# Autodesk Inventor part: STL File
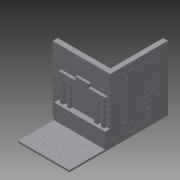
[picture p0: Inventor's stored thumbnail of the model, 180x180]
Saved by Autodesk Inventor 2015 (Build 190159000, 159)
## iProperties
Created: 2015-05
Part Number: STL File
Material: Generic
Document SubType Name: Modeling
Designer: TREINA5
Density: 1 g/cm^3
Appearance: Default
Author: TREINA5
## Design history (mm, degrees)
derived "Montagem.iam"
body "Solid1"
node "Parede.ipt:1"
node "Azulejo (1).ipt:1"
node "Azulejo (1).ipt:2"
node "Azulejo (1).ipt:3"
node "Azulejo (1).ipt:4"
node "Azulejo (1).ipt:5"
node "Azulejo (1).ipt:6"
node "Azulejo (1).ipt:7"
node "Azulejo (1).ipt:8"
node "Azulejo (1).ipt:9"
node "Azulejo (1).ipt:10"
node "Azulejo (1).ipt:11"
node "Azulejo (1).ipt:12"
node "Azulejo (1).ipt:13"
node "Azulejo (1).ipt:14"
node "Azulejo (1).ipt:15"
node "Azulejo (1).ipt:16"
node "Azulejo (1).ipt:17"
node "Azulejo (1).ipt:20"
node "Azulejo (1).ipt:21"
node "Azulejo (1).ipt:22"
node "Azulejo (1).ipt:23"
node "Azulejo (1).ipt:24"
node "Azulejo (1).ipt:25"
node "Azulejo (1).ipt:26"
node "Azulejo (1).ipt:27"
node "Azulejo (1).ipt:30"
node "Azulejo (1).ipt:31"
node "Azulejo (1).ipt:32"
node "Azulejo (9).ipt:2"
node "Azulejo (10).ipt:1"
node "Azulejo (10).ipt:2"
node "Azulejo (9).ipt:3"
node "Azulejo (9).ipt:4"
node "Azulejo (9).ipt:5"
node "Azulejo (1).ipt:33"
node "Azulejo (1).ipt:34"
node "Azulejo (1).ipt:35"
node "Azulejo (1).ipt:36"
node "Azulejo (1).ipt:37"
node "Azulejo (1).ipt:38"
node "Azulejo (1).ipt:39"
node "Azulejo (1).ipt:40"
node "Azulejo (1).ipt:41"
node "Azulejo (1).ipt:44"
node "Azulejo (1).ipt:48"
node "Azulejo (1).ipt:49"
node "Azulejo (3).ipt:1"
node "Azulejo (2).ipt:1"
node "Azulejo (4).ipt:1"
node "Azulejo (5).ipt:1"
node "Azulejo (5).ipt:2"
node "Azulejo (5).ipt:3"
node "Azulejo (5).ipt:4"
node "Azulejo (5).ipt:5"
node "Azulejo (5).ipt:6"
node "Azulejo (5).ipt:7"
node "Azulejo (7).ipt:1"
node "Azulejo (5).ipt:8"
node "Azulejo (5).ipt:9"
node "Azulejo (5).ipt:10"
node "Azulejo (5).ipt:11"
node "Azulejo (1).ipt:50"
node "Azulejo (2).ipt:2"
node "Azulejo (2).ipt:3"
node "Azulejo (6).ipt:1"
node "Azulejo (2).ipt:4"
node "Azulejo (2).ipt:5"
node "Azulejo (2).ipt:6"
node "Azulejo (8).ipt:1"
node "Azulejo (8).ipt:2"
node "Azulejo (1).ipt:51"
node "Azulejo (1).ipt:52"
node "Azulejo (1).ipt:53"
node "Azulejo (1).ipt:54"
node "Azulejo (1).ipt:55"
node "Azulejo (1).ipt:56"
node "Azulejo (1).ipt:57"
node "Azulejo (1).ipt:58"
node "Azulejo (1).ipt:59"
node "Azulejo (1).ipt:60"
node "Azulejo (1).ipt:61"
node "Azulejo (1).ipt:62"
node "Azulejo (1).ipt:63"
node "Azulejo (1).ipt:64"
node "Azulejo (1).ipt:65"
node "Azulejo (1).ipt:66"
node "Azulejo (1).ipt:67"
node "Azulejo (1).ipt:68"
node "Azulejo (1).ipt:69"
node "Azulejo (1).ipt:70"
node "Azulejo (1).ipt:73"
node "Azulejo (1).ipt:74"
node "Azulejo (1).ipt:75"
node "Azulejo (1).ipt:76"
node "Azulejo (1).ipt:77"
node "Azulejo (1).ipt:78"
node "Azulejo (1).ipt:79"
node "Azulejo (1).ipt:80"
node "Azulejo (1).ipt:81"
node "Azulejo (1).ipt:82"
node "Azulejo (1).ipt:83"
node "Azulejo (1).ipt:84"
node "Azulejo (1).ipt:85"
node "Azulejo (1).ipt:86"
node "Azulejo (1).ipt:87"
node "Azulejo (1).ipt:88"
node "Azulejo (1).ipt:89"
node "Azulejo (1).ipt:90"
node "Azulejo (1).ipt:91"
node "Azulejo (1).ipt:92"
node "Azulejo (1).ipt:93"
node "Azulejo (1).ipt:94"
node "Azulejo (1).ipt:95"
node "Azulejo (1).ipt:96"
node "Azulejo (1).ipt:97"
node "Azulejo (1).ipt:98"
node "Azulejo (1).ipt:99"
node "Azulejo (1).ipt:100"
node "Azulejo (1).ipt:101"
node "Azulejo (1).ipt:102"
node "Azulejo (1).ipt:103"
node "Azulejo (1).ipt:104"
node "Azulejo (1).ipt:105"
node "Azulejo (1).ipt:106"
node "Azulejo (1).ipt:107"
node "Azulejo (1).ipt:108"
node "Azulejo (1).ipt:109"
node "Azulejo (1).ipt:110"
node "Azulejo (1).ipt:111"
node "Azulejo (1).ipt:112"
node "Azulejo (1).ipt:113"
node "Azulejo (1).ipt:114"
node "Azulejo (1).ipt:115"
node "Azulejo (1).ipt:116"
node "Azulejo (1).ipt:117"
node "Azulejo (1).ipt:118"
node "Azulejo (1).ipt:119"
node "Azulejo (1).ipt:120"
node "Azulejo (1).ipt:121"
node "Azulejo (1).ipt:122"
node "Azulejo (1).ipt:123"
node "Azulejo (1).ipt:124"
node "Azulejo (1).ipt:125"
node "Azulejo (1).ipt:126"
node "Azulejo (1).ipt:127"
node "Azulejo (1).ipt:128"
node "Azulejo (1).ipt:129"
node "Azulejo (1).ipt:130"
node "Azulejo (1).ipt:131"
node "Azulejo (1).ipt:132"
node "Azulejo (1).ipt:133"
node "Azulejo (1).ipt:134"
node "Azulejo (1).ipt:136"
node "Azulejo (1).ipt:137"
node "Azulejo (1).ipt:138"
node "Azulejo (1).ipt:140"
node "Azulejo (11).ipt:1"
node "Azulejo (12).ipt:1"
node "Azulejo (13).ipt:1"
node "Azulejo (14).ipt:1"
node "Azulejo (15).ipt:1"
node "Azulejo (16).ipt:1"
node "Azulejo (1).ipt:141"
node "Azulejo (1).ipt:142"
node "Azulejo (1).ipt:143"
node "Azulejo (1).ipt:144"
node "Azulejo (1).ipt:145"
node "Azulejo (1).ipt:146"
node "Azulejo (17).ipt:1"
node "Azulejo (18).ipt:1"
node "Azulejo (19).ipt:1"
node "Azulejo (20).ipt:1"
node "Azulejo (21).ipt:1"
node "Azulejo (22).ipt:1"
node "Azulejo (1).ipt:147"
node "Azulejo (1).ipt:148"
node "Azulejo (1).ipt:149"
node "Azulejo (23).ipt:1"
node "Azulejo (24).ipt:1"
node "Azulejo (25).ipt:2"
node "Azulejo (26).ipt:1"
node "Azulejo (27).ipt:1"
node "Azulejo (28).ipt:1"
node "Azulejo (29).ipt:1"
node "Azulejo (30).ipt:1"
node "Azulejo (31).ipt:1"
node "Azulejo (32).ipt:1"
node "Azulejo (33).ipt:1"
node "Azulejo (34).ipt:1"
node "Azulejo (35).ipt:1"
node "Azulejo (36).ipt:1"
node "Azulejo (37).ipt:1"
node "Azulejo (38).ipt:1"
node "Azulejo (39).ipt:1"
node "Azulejo (40).ipt:1"
node "Azulejo (41).ipt:1"
node "Azulejo (42).ipt:1"
node "Azulejo (43).ipt:1"
node "Azulejo (44).ipt:1"
node "Azulejo (1).ipt:150"
node "Azulejo (36).ipt:2"
node "Azulejo (37).ipt:2"
node "Azulejo (42).ipt:2"
node "Azulejo (42).ipt:3"
node "Azulejo (44).ipt:2"
node "Azulejo (10).ipt:3"
node "Azulejo (9).ipt:6"
node "Azulejo (9).ipt:7"
node "Azulejo (1).ipt:151"
node "Azulejo (1).ipt:152"
node "Azulejo (1).ipt:153"
node "Azulejo (1).ipt:154"
node "Azulejo (1).ipt:155"
node "Azulejo (1).ipt:156"
node "Azulejo (1).ipt:157"
node "Azulejo (1).ipt:158"
node "Azulejo (1).ipt:159"
node "Azulejo (1).ipt:160"
node "Azulejo (1).ipt:161"
node "Azulejo (1).ipt:162"
node "Azulejo (1).ipt:163"
node "Azulejo (1).ipt:164"
node "Azulejo (1).ipt:165"
node "Azulejo (6).ipt:2"
node "Azulejo (6).ipt:3"
node "Azulejo (53).ipt:1"
node "Azulejo (53).ipt:2"
node "Azulejo (52).ipt:1"
node "Azulejo (52).ipt:2"
node "Azulejo (53).ipt:3"
node "Azulejo (53).ipt:4"
node "Azulejo (54).ipt:1"
node "Azulejo (54).ipt:2"
node "Azulejo (55).ipt:1"
node "Azulejo (51).ipt:2"
node "Azulejo (55).ipt:2"
node "Azulejo (51).ipt:3"
node "Azulejo (55).ipt:3"
node "Azulejo (55).ipt:4"
node "Azulejo (55).ipt:5"
node "Azulejo (55).ipt:6"
node "Azulejo (55).ipt:7"
node "Azulejo (55).ipt:8"
node "Azulejo (55).ipt:9"
node "Azulejo (55).ipt:10"
node "Azulejo (55).ipt:11"
node "Azulejo (55).ipt:12"
node "Azulejo (55).ipt:13"
node "Azulejo (55).ipt:14"
node "Azulejo (55).ipt:15"
node "Azulejo (55).ipt:16"
node "Azulejo (55).ipt:17"
node "Azulejo (55).ipt:18"
node "Azulejo (56).ipt:1"
node "Azulejo (56).ipt:2"
node "Azulejo (49).ipt:1"
node "Azulejo (49).ipt:2"
node "Azulejo (49).ipt:3"
node "Azulejo (49).ipt:4"
node "Azulejo (1).ipt:166"
node "Azulejo (1).ipt:167"
node "Azulejo (1).ipt:168"
node "Azulejo (1).ipt:169"
node "Azulejo (1).ipt:170"
node "Azulejo (1).ipt:171"
node "Azulejo (1).ipt:172"
node "Azulejo (1).ipt:173"
node "Azulejo (1).ipt:174"
node "Azulejo (1).ipt:175"
node "Azulejo (1).ipt:176"
node "Azulejo (1).ipt:177"
node "Azulejo (1).ipt:178"
node "Azulejo (1).ipt:179"
node "Azulejo (1).ipt:180"
node "Azulejo (1).ipt:181"
node "Azulejo (1).ipt:182"
node "Azulejo (1).ipt:183"
node "Azulejo (1).ipt:184"
node "Azulejo (1).ipt:185"
node "Azulejo (1).ipt:186"
node "Azulejo (1).ipt:187"
node "Azulejo (1).ipt:188"
node "Azulejo (1).ipt:189"
node "Azulejo (1).ipt:190"
node "Azulejo (1).ipt:191"
node "Azulejo (1).ipt:192"
node "Azulejo (1).ipt:193"
node "Azulejo (45).ipt:1"
node "Azulejo (45).ipt:2"
node "Azulejo (45).ipt:3"
node "Azulejo (45).ipt:4"
node "Azulejo (57).ipt:1"
node "Azulejo (57).ipt:2"
node "Azulejo (51).ipt:4"
node "Azulejo (51).ipt:5"
node "Azulejo (51).ipt:6"
node "Azulejo (51).ipt:7"
node "Azulejo (51).ipt:8"
node "Azulejo (51).ipt:9"
node "Azulejo (51).ipt:10"
node "Azulejo (51).ipt:11"
node "Azulejo (51).ipt:12"
node "Azulejo (51).ipt:13"
node "Azulejo (51).ipt:14"
node "Azulejo (51).ipt:15"
node "Azulejo (51).ipt:16"
node "Azulejo (51).ipt:17"
node "Azulejo (51).ipt:18"
node "Azulejo (51).ipt:19"
node "Azulejo (51).ipt:20"
node "Azulejo (51).ipt:21"
node "Azulejo (51).ipt:22"
node "Azulejo (51).ipt:23"
node "Azulejo (51).ipt:24"
node "Azulejo (51).ipt:25"
node "Azulejo (51).ipt:26"
node "Azulejo (51).ipt:27"
node "Azulejo (51).ipt:28"
node "Azulejo (51).ipt:29"
node "Azulejo (51).ipt:30"
node "Azulejo (51).ipt:31"
node "Azulejo (51).ipt:32"
node "Azulejo (51).ipt:33"
node "Azulejo (51).ipt:34"
node "Azulejo (51).ipt:35"
node "Azulejo (48).ipt:1"
node "Azulejo (48).ipt:2"
node "Azulejo (47).ipt:2"
node "Azulejo (47).ipt:3"
node "Azulejo (47).ipt:5"
node "Azulejo (47).ipt:6"
node "Azulejo (46).ipt:1"
node "Azulejo (46).ipt:2"
node "Azulejo (1).ipt:194"
node "Azulejo (1).ipt:195"
node "Azulejo (1).ipt:196"
node "Azulejo (1).ipt:197"
node "Azulejo (1).ipt:198"
node "Azulejo (1).ipt:199"
node "Azulejo (1).ipt:200"
node "Azulejo (1).ipt:201"
node "Azulejo (1).ipt:202"
node "Azulejo (1).ipt:203"
node "Azulejo (54).ipt:3"
node "Azulejo (54).ipt:4"
node "Azulejo (54).ipt:5"
node "Azulejo (54).ipt:6"
node "Azulejo (54).ipt:7"
node "Azulejo (54).ipt:8"
node "Azulejo (54).ipt:9"
node "Azulejo (54).ipt:10"
node "Azulejo (54).ipt:11"
node "Azulejo (54).ipt:12"
node "Azulejo (54).ipt:13"
node "Azulejo (54).ipt:14"
node "Azulejo (54).ipt:15"
node "Azulejo (54).ipt:16"
node "Azulejo (54).ipt:17"
node "Azulejo (50).ipt:1"
node "Azulejo (50).ipt:2"
node "Azulejo (50).ipt:3"
node "Azulejo (50).ipt:4"
node "Azulejo (50).ipt:5"
node "Azulejo (50).ipt:6"
node "Azulejo (50).ipt:7"
node "Azulejo (50).ipt:8"
node "Azulejo (50).ipt:9"
node "Azulejo (50).ipt:10"
node "Azulejo (50).ipt:11"
node "Azulejo (50).ipt:12"
node "Azulejo (50).ipt:13"
node "Azulejo (50).ipt:14"
node "Azulejo (50).ipt:15"
node "Azulejo (50).ipt:16"
node "Azulejo (58).ipt:1"
node "Azulejo (58).ipt:2"
node "Azulejo (58).ipt:3"
node "Azulejo (58).ipt:4"
node "Azulejo (58).ipt:5"
node "Azulejo (58).ipt:6"
node "Azulejo (58).ipt:7"
node "Azulejo (58).ipt:8"
node "Azulejo (54).ipt:18"
node "Azulejo (54).ipt:19"
node "Azulejo (54).ipt:20"
node "Azulejo (54).ipt:21"
node "Azulejo (54).ipt:22"
node "Azulejo (54).ipt:23"
node "Azulejo (54).ipt:24"
node "Azulejo (54).ipt:25"
node "Azulejo (54).ipt:26"
node "Azulejo (54).ipt:27"
node "Azulejo (54).ipt:28"
node "Azulejo (54).ipt:29"
node "Azulejo (54).ipt:30"
node "Azulejo (54).ipt:31"
node "Azulejo (54).ipt:32"
node "Azulejo (54).ipt:33"
node "Azulejo (54).ipt:34"
node "Azulejo (51).ipt:36"
node "Azulejo (51).ipt:37"
node "Azulejo (51).ipt:38"
node "Azulejo (51).ipt:39"
node "Azulejo (51).ipt:40"
node "Azulejo (51).ipt:41"
node "Azulejo (61).ipt:1"
node "Azulejo (61).ipt:2"
node "Azulejo (60).ipt:1"
node "Azulejo (60).ipt:2"
node "Azulejo (59).ipt:1"
node "Azulejo (59).ipt:2"
node "Azulejo (62).ipt:1"
node "Azulejo (62).ipt:2"
node "Azulejo (63).ipt:1"
node "Azulejo (63).ipt:2"
node "Montagem.iam_Bodies"
